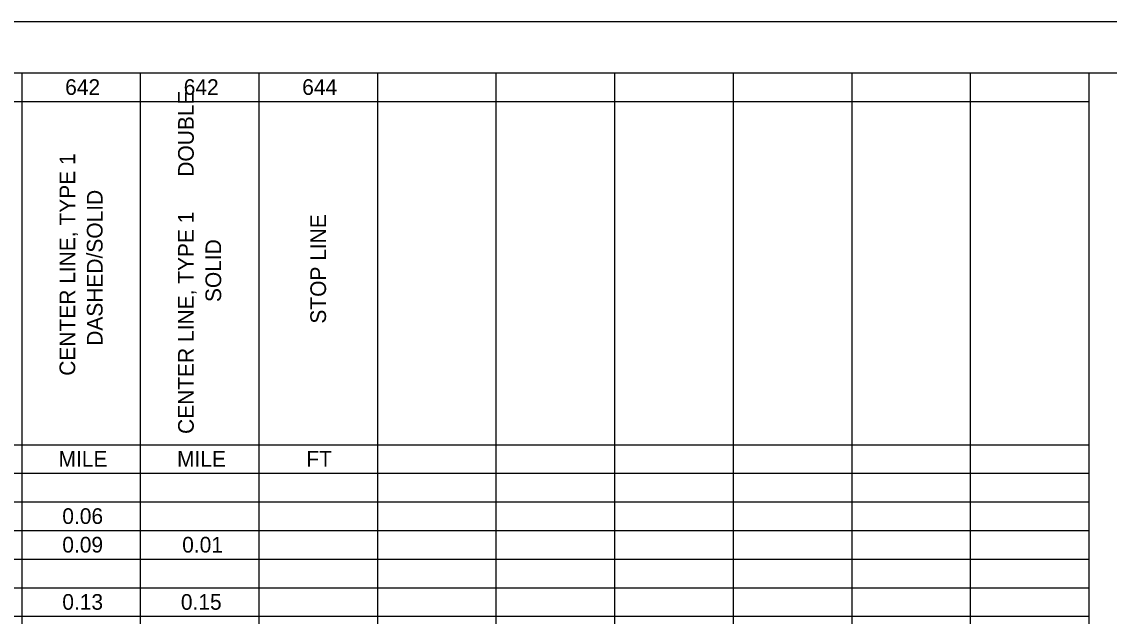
# Model space of a CAD drawing. Extents: x 0 to 34, y 0 to 22.
# Drawn here: x 14.06 to 24.7, y 16.18 to 22 of the extents above; entities that cross this region are included whole.
import ezdxf

# ---------------------------------------------------------------- set-up
doc = ezdxf.new("R2010")
doc.units = 0
for name, color, linetype in [('SH_Border', 7, 'Continuous'), ('SH_Cut_Line', 7, 'Continuous'), ('SH_Text', 7, 'Continuous')]:
    doc.layers.add(name, color=color, linetype=linetype)

msp = doc.modelspace()

# ---------------------------------------------------------------- linework, layer by layer
at = {"layer": 'SH_Border'}
msp.add_lwpolyline([(1.5, 21.5), (33.5, 21.5), (33.5, 0.5), (1.5, 0.5)], close=True, dxfattribs=at)
at = {"layer": 'SH_Cut_Line'}
msp.add_lwpolyline([(0, 0), (34, 0), (34, 22), (0, 22)], close=True, dxfattribs=at)
at = {"layer": 'SH_Text'}
for p, q in [((3.02, 21.5), (14.06, 21.5)), ((14.06, 21.5), (16.38, 21.5)), ((14.06, 21.5), (14.06, 21.22)), ((15.22, 21.5), (15.22, 21.22)), ((16.38, 21.5), (21.02, 21.5)), ((16.38, 21.5), (16.38, 21.22)), ((17.54, 21.5), (17.54, 21.22)), ((18.7, 21.5), (18.7, 21.22)), ((19.86, 21.5), (19.86, 21.22)), ((21.02, 21.5), (23.34, 21.5)), ((21.02, 21.5), (21.02, 21.22)), ((22.18, 21.5), (22.18, 21.22)), ((23.34, 21.5), (24.5, 21.5)), ((23.34, 21.5), (23.34, 21.22)), ((24.5, 21.5), (24.5, 21.22)), ((5.94, 21.22), (14.06, 21.22)), ((14.06, 21.22), (16.38, 21.22)), ((14.06, 21.22), (14.06, 20.94)), ((15.22, 21.22), (15.22, 20.94)), ((16.38, 21.22), (21.02, 21.22)), ((16.38, 21.22), (16.38, 20.94)), ((17.54, 21.22), (17.54, 20.94)), ((18.7, 21.22), (18.7, 20.94)), ((19.86, 21.22), (19.86, 20.94)), ((21.02, 21.22), (23.34, 21.22)), ((21.02, 21.22), (21.02, 20.94)), ((22.18, 21.22), (22.18, 20.94)), ((23.34, 21.22), (24.5, 21.22)), ((23.34, 21.22), (23.34, 20.94)), ((24.5, 21.22), (24.5, 20.94)), ((14.06, 20.94), (14.06, 20.66)), ((15.22, 20.94), (15.22, 20.66)), ((16.38, 20.94), (16.38, 20.66)), ((17.54, 20.94), (17.54, 20.66)), ((18.7, 20.94), (18.7, 20.66)), ((19.86, 20.94), (19.86, 20.66)), ((21.02, 20.94), (21.02, 20.66)), ((22.18, 20.94), (22.18, 20.66)), ((23.34, 20.94), (23.34, 20.66)), ((24.5, 20.94), (24.5, 20.66)), ((14.06, 20.66), (14.06, 20.38)), ((15.22, 20.66), (15.22, 20.38)), ((16.38, 20.66), (16.38, 20.38)), ((17.54, 20.66), (17.54, 20.38)), ((18.7, 20.66), (18.7, 20.38)), ((19.86, 20.66), (19.86, 20.38)), ((21.02, 20.66), (21.02, 20.38)), ((22.18, 20.66), (22.18, 20.38)), ((23.34, 20.66), (23.34, 20.38)), ((24.5, 20.66), (24.5, 20.38)), ((14.06, 20.38), (14.06, 20.1)), ((15.22, 20.38), (15.22, 20.1)), ((16.38, 20.38), (16.38, 20.1)), ((17.54, 20.38), (17.54, 20.1)), ((18.7, 20.38), (18.7, 20.1)), ((19.86, 20.38), (19.86, 20.1)), ((21.02, 20.38), (21.02, 20.1)), ((22.18, 20.38), (22.18, 20.1)), ((23.34, 20.38), (23.34, 20.1)), ((24.5, 20.38), (24.5, 20.1)), ((14.06, 20.1), (14.06, 19.82)), ((15.22, 20.1), (15.22, 19.82)), ((16.38, 20.1), (16.38, 19.82)), ((17.54, 20.1), (17.54, 19.82)), ((18.7, 20.1), (18.7, 19.82)), ((19.86, 20.1), (19.86, 19.82)), ((21.02, 20.1), (21.02, 19.82)), ((22.18, 20.1), (22.18, 19.82)), ((23.34, 20.1), (23.34, 19.82)), ((24.5, 20.1), (24.5, 19.82)), ((14.06, 19.82), (14.06, 19.54)), ((15.22, 19.82), (15.22, 19.54)), ((16.38, 19.82), (16.38, 19.54)), ((17.54, 19.82), (17.54, 19.54)), ((18.7, 19.82), (18.7, 19.54)), ((19.86, 19.82), (19.86, 19.54)), ((21.02, 19.82), (21.02, 19.54)), ((22.18, 19.82), (22.18, 19.54)), ((23.34, 19.82), (23.34, 19.54)), ((24.5, 19.82), (24.5, 19.54)), ((14.06, 19.54), (14.06, 19.26)), ((15.22, 19.54), (15.22, 19.26)), ((16.38, 19.54), (16.38, 19.26)), ((17.54, 19.54), (17.54, 19.26)), ((18.7, 19.54), (18.7, 19.26)), ((19.86, 19.54), (19.86, 19.26)), ((21.02, 19.54), (21.02, 19.26)), ((22.18, 19.54), (22.18, 19.26)), ((23.34, 19.54), (23.34, 19.26)), ((24.5, 19.54), (24.5, 19.26)), ((14.06, 19.26), (14.06, 18.98)), ((15.22, 19.26), (15.22, 18.98)), ((16.38, 19.26), (16.38, 18.98)), ((17.54, 19.26), (17.54, 18.98)), ((18.7, 19.26), (18.7, 18.98)), ((19.86, 19.26), (19.86, 18.98)), ((21.02, 19.26), (21.02, 18.98)), ((22.18, 19.26), (22.18, 18.98)), ((23.34, 19.26), (23.34, 18.98)), ((24.5, 19.26), (24.5, 18.98)), ((14.06, 18.98), (14.06, 18.7)), ((15.22, 18.98), (15.22, 18.7)), ((16.38, 18.98), (16.38, 18.7)), ((17.54, 18.98), (17.54, 18.7)), ((18.7, 18.98), (18.7, 18.7)), ((19.86, 18.98), (19.86, 18.7)), ((21.02, 18.98), (21.02, 18.7)), ((22.18, 18.98), (22.18, 18.7)), ((23.34, 18.98), (23.34, 18.7)), ((24.5, 18.98), (24.5, 18.7)), ((14.06, 18.7), (14.06, 18.42)), ((15.22, 18.7), (15.22, 18.42)), ((16.38, 18.7), (16.38, 18.42)), ((17.54, 18.7), (17.54, 18.42)), ((18.7, 18.7), (18.7, 18.42)), ((19.86, 18.7), (19.86, 18.42)), ((21.02, 18.7), (21.02, 18.42)), ((22.18, 18.7), (22.18, 18.42)), ((23.34, 18.7), (23.34, 18.42)), ((24.5, 18.7), (24.5, 18.42)), ((14.06, 18.42), (14.06, 18.14)), ((15.22, 18.42), (15.22, 18.14)), ((16.38, 18.42), (16.38, 18.14)), ((17.54, 18.42), (17.54, 18.14)), ((18.7, 18.42), (18.7, 18.14)), ((19.86, 18.42), (19.86, 18.14)), ((21.02, 18.42), (21.02, 18.14)), ((22.18, 18.42), (22.18, 18.14)), ((23.34, 18.42), (23.34, 18.14)), ((24.5, 18.42), (24.5, 18.14)), ((14.06, 18.14), (14.06, 17.86)), ((15.22, 18.14), (15.22, 17.86)), ((16.38, 18.14), (16.38, 17.86)), ((17.54, 18.14), (17.54, 17.86)), ((18.7, 18.14), (18.7, 17.86)), ((19.86, 18.14), (19.86, 17.86)), ((21.02, 18.14), (21.02, 17.86)), ((22.18, 18.14), (22.18, 17.86)), ((23.34, 18.14), (23.34, 17.86)), ((24.5, 18.14), (24.5, 17.86)), ((5.94, 17.86), (14.06, 17.86)), ((14.06, 17.86), (16.38, 17.86)), ((14.06, 17.86), (14.06, 17.58)), ((15.22, 17.86), (15.22, 17.58)), ((16.38, 17.86), (21.02, 17.86)), ((16.38, 17.86), (16.38, 17.58)), ((17.54, 17.86), (17.54, 17.58)), ((18.7, 17.86), (18.7, 17.58)), ((19.86, 17.86), (19.86, 17.58)), ((21.02, 17.86), (23.34, 17.86)), ((21.02, 17.86), (21.02, 17.58)), ((22.18, 17.86), (22.18, 17.58)), ((23.34, 17.86), (24.5, 17.86)), ((23.34, 17.86), (23.34, 17.58)), ((24.5, 17.86), (24.5, 17.58)), ((3.02, 17.58), (14.06, 17.58)), ((14.06, 17.58), (16.38, 17.58)), ((14.06, 17.58), (14.06, 17.3)), ((15.22, 17.58), (15.22, 17.3)), ((16.38, 17.58), (21.02, 17.58)), ((16.38, 17.58), (16.38, 17.3)), ((17.54, 17.58), (17.54, 17.3)), ((18.7, 17.58), (18.7, 17.3)), ((19.86, 17.58), (19.86, 17.3)), ((21.02, 17.58), (23.34, 17.58)), ((21.02, 17.58), (21.02, 17.3)), ((22.18, 17.58), (22.18, 17.3)), ((23.34, 17.58), (24.5, 17.58)), ((23.34, 17.58), (23.34, 17.3)), ((24.5, 17.58), (24.5, 17.3)), ((3.02, 17.3), (14.06, 17.3)), ((14.06, 17.3), (16.38, 17.3)), ((14.06, 17.3), (14.06, 17.02)), ((15.22, 17.3), (15.22, 17.02)), ((16.38, 17.3), (21.02, 17.3)), ((16.38, 17.3), (16.38, 17.02)), ((17.54, 17.3), (17.54, 17.02)), ((18.7, 17.3), (18.7, 17.02)), ((19.86, 17.3), (19.86, 17.02)), ((21.02, 17.3), (23.34, 17.3)), ((21.02, 17.3), (21.02, 17.02)), ((22.18, 17.3), (22.18, 17.02)), ((23.34, 17.3), (24.5, 17.3)), ((23.34, 17.3), (23.34, 17.02)), ((24.5, 17.3), (24.5, 17.02)), ((3.02, 17.02), (14.06, 17.02)), ((14.06, 17.02), (16.38, 17.02)), ((14.06, 17.02), (14.06, 16.74)), ((15.22, 17.02), (15.22, 16.74)), ((16.38, 17.02), (21.02, 17.02)), ((16.38, 17.02), (16.38, 16.74)), ((17.54, 17.02), (17.54, 16.74)), ((18.7, 17.02), (18.7, 16.74)), ((19.86, 17.02), (19.86, 16.74)), ((21.02, 17.02), (23.34, 17.02)), ((21.02, 17.02), (21.02, 16.74)), ((22.18, 17.02), (22.18, 16.74)), ((23.34, 17.02), (24.5, 17.02)), ((23.34, 17.02), (23.34, 16.74)), ((24.5, 17.02), (24.5, 16.74)), ((3.02, 16.74), (14.06, 16.74)), ((14.06, 16.74), (16.38, 16.74)), ((14.06, 16.74), (14.06, 16.46)), ((15.22, 16.74), (15.22, 16.46)), ((16.38, 16.74), (21.02, 16.74)), ((16.38, 16.74), (16.38, 16.46)), ((17.54, 16.74), (17.54, 16.46)), ((18.7, 16.74), (18.7, 16.46)), ((19.86, 16.74), (19.86, 16.46)), ((21.02, 16.74), (23.34, 16.74)), ((21.02, 16.74), (21.02, 16.46)), ((22.18, 16.74), (22.18, 16.46)), ((23.34, 16.74), (24.5, 16.74)), ((23.34, 16.74), (23.34, 16.46)), ((24.5, 16.74), (24.5, 16.46)), ((3.02, 16.46), (14.06, 16.46)), ((14.06, 16.46), (16.38, 16.46)), ((14.06, 16.46), (14.06, 16.18)), ((15.22, 16.46), (15.22, 16.18)), ((16.38, 16.46), (21.02, 16.46)), ((16.38, 16.46), (16.38, 16.18)), ((17.54, 16.46), (17.54, 16.18)), ((18.7, 16.46), (18.7, 16.18)), ((19.86, 16.46), (19.86, 16.18)), ((21.02, 16.46), (23.34, 16.46)), ((21.02, 16.46), (21.02, 16.18)), ((22.18, 16.46), (22.18, 16.18)), ((23.34, 16.46), (24.5, 16.46)), ((23.34, 16.46), (23.34, 16.18)), ((24.5, 16.46), (24.5, 16.18)), ((3.02, 16.18), (14.06, 16.18)), ((14.06, 16.18), (16.38, 16.18)), ((14.06, 16.18), (14.06, 15.9)), ((15.22, 16.18), (15.22, 15.9)), ((16.38, 16.18), (21.02, 16.18)), ((16.38, 16.18), (16.38, 15.9)), ((17.54, 16.18), (17.54, 15.9)), ((18.7, 16.18), (18.7, 15.9)), ((19.86, 16.18), (19.86, 15.9)), ((21.02, 16.18), (23.34, 16.18)), ((21.02, 16.18), (21.02, 15.9)), ((22.18, 16.18), (22.18, 15.9)), ((23.34, 16.18), (24.5, 16.18)), ((23.34, 16.18), (23.34, 15.9)), ((24.5, 16.18), (24.5, 15.9))]:
    msp.add_line(p, q, dxfattribs=at)

# ---------------------------------------------------------------- texts
for s, p in [('642', (14.485, 21.284)), ('642', (15.645, 21.284)), ('644', (16.804, 21.284)), ('MILE', (14.42, 17.644)), ('MILE', (15.58, 17.644)), ('FT', (16.844, 17.644)), ('0.06', (14.457, 17.084)), ('0.09', (14.457, 16.804)), ('0.01', (15.63, 16.804)), ('0.13', (14.457, 16.244)), ('0.15', (15.617, 16.244))]:
    msp.add_text(s, height=0.1533, dxfattribs=at).set_placement(p)
for s, height, p in [('CENTER LINE, TYPE 1      DOUBLE ', 0.15334, (15.743, 17.965)), ('CENTER LINE, TYPE 1 ', 0.15334, (14.583, 18.535)), ('DASHED/SOLID', 0.15334, (14.851, 18.828)), ('STOP LINE', 0.1533, (17.037, 19.045)), ('SOLID', 0.1533, (16.011, 19.256))]:
    msp.add_text(s, height=height, rotation=90, dxfattribs=at).set_placement(p)

doc.saveas('drawing.dxf')
